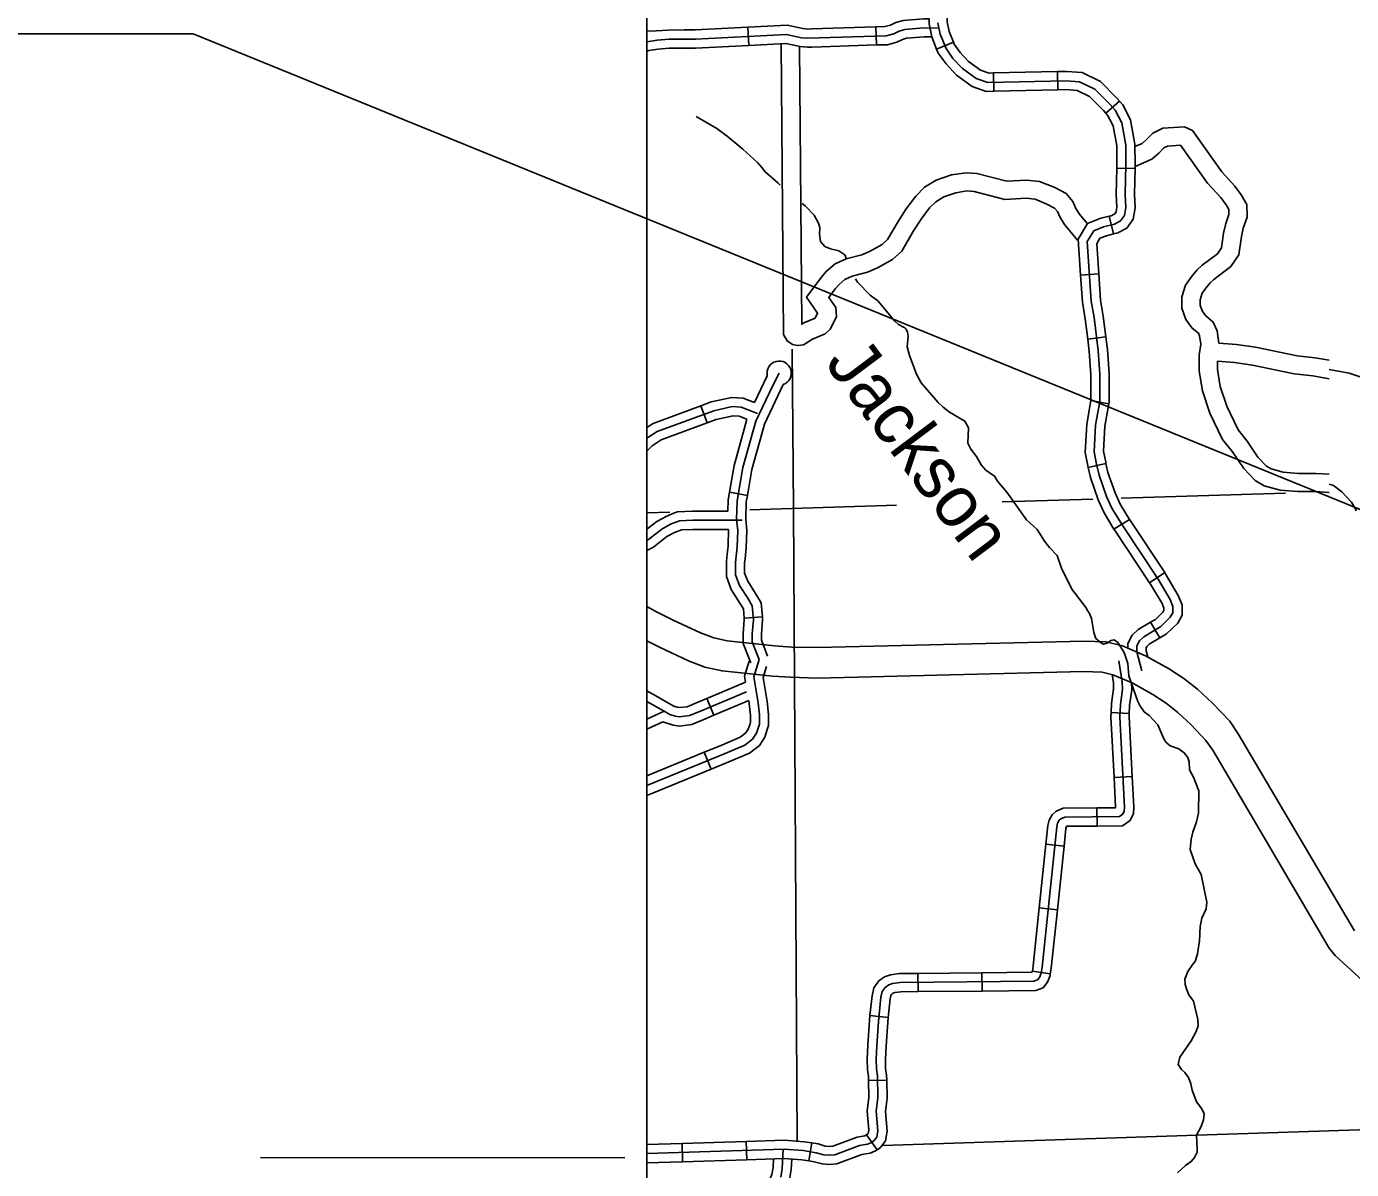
# Model space of a CAD drawing. Extents: x 1212896 to 1368412, y 378476 to 478763.
# Drawn here: x 1252291 to 1263202, y 405588 to 414998 of the extents above; entities that cross this region are included whole.
import ezdxf

# ---------------------------------------------------------------- set-up
doc = ezdxf.new("R2010")
doc.units = 0
for name, color, linetype in [('1', 7, 'Continuous'), ('Level 10', 7, 'Continuous'), ('Level 32', 7, 'Continuous'), ('Level 35', 7, 'Continuous'), ('Level 4', 7, 'Continuous'), ('Level 45', 7, 'Continuous'), ('Level 46', 7, 'Continuous'), ('Level 5', 7, 'Continuous'), ('R_Draft', 7, 'Continuous')]:
    doc.layers.add(name, color=color, linetype=linetype)

msp = doc.modelspace()

# ---------------------------------------------------------------- linework, layer by layer
at = {"layer": '1'}
msp.add_line((1254217, 405685), (1257217, 405684), dxfattribs=at)
msp.add_lwpolyline([(1257400, 437504), (1319317, 437504), (1319317, 388319), (1257400, 388319)], close=True, dxfattribs=at)
at = {"layer": 'Level 10'}
for points in [[(1258450, 409899), (1258060, 409939), (1257951, 409964), (1257842, 410006), (1257617, 410111), (1257474, 410181), (1257400, 410222)], [(1257400, 409939), (1257509, 409886), (1257743, 409776), (1257878, 409724), (1258019, 409692), (1258434, 409650)], [(1263226, 407553), (1262270, 409174), (1262199, 409278), (1262058, 409427), (1261934, 409541), (1261822, 409630), (1261694, 409713), (1261505, 409818), (1261317, 409899), (1261181, 409932), (1260997, 409938), (1258804, 409884), (1258593, 409889), (1258450, 409899)], [(1258434, 409650), (1258582, 409640), (1258804, 409634), (1260996, 409688), (1261148, 409683), (1261238, 409661), (1261395, 409594), (1261565, 409499), (1261676, 409426), (1261772, 409350), (1261882, 409249), (1262004, 409121), (1262059, 409040), (1263019, 407411), (1263068, 407350), (1265195, 405400)]]:
    msp.add_lwpolyline(points, dxfattribs=at)
at = {"layer": 'Level 32'}
for p, q in [((1259785, 414813), (1259925, 414869)), ((1260257, 414466), (1260254, 414616)), ((1260785, 414477), (1260782, 414627)), ((1261178, 414286), (1261293, 414383)), ((1261270, 413831), (1261420, 413828)), ((1261207, 413436), (1261242, 413290)), ((1260971, 412952), (1261121, 412962)), ((1261030, 412423), (1261179, 412442)), ((1261057, 411919), (1261204, 411892)), ((1261033, 411367), (1261180, 411399)), ((1261246, 410861), (1261374, 410940)), ((1261539, 410419), (1261664, 410502)), ((1261548, 410094), (1261625, 409965)), ((1261222, 409350), (1261372, 409343)), ((1261247, 408815), (1261397, 408823)), ((1261106, 408565), (1261108, 408415)), ((1260686, 408267), (1260835, 408251)), ((1260631, 407742), (1260780, 407726)), ((1260574, 407220), (1260722, 407198)), ((1259631, 407202), (1259633, 407052)), ((1260159, 407207), (1260161, 407057)), ((1259237, 406855), (1259387, 406840)), ((1259225, 406319), (1259375, 406323)), ((1257689, 405801), (1257694, 405651)), ((1258217, 405818), (1258222, 405668)), ((1258757, 405806), (1258734, 405658)), ((1259209, 405873), (1259296, 405750))]:
    msp.add_line(p, q, dxfattribs=at)
for points in [[(1259726, 415362), (1259719, 415178), (1259724, 415020), (1259745, 414914), (1259785, 414813)], [(1259876, 415356), (1259869, 415178), (1259873, 415037), (1259889, 414957), (1259925, 414869)], [(1259797, 415028), (1259816, 414935), (1259863, 414816), (1259920, 414736), (1259998, 414653), (1260112, 414571), (1260207, 414538), (1260852, 414552), (1260962, 414544), (1261089, 414483), (1261215, 414356), (1261256, 414309), (1261310, 414205), (1261343, 414022), (1261345, 413863), (1261338, 413616), (1261345, 413508), (1261333, 413442), (1261301, 413397), (1261250, 413371), (1261161, 413349), (1261079, 413316)], [(1259925, 414869), (1259931, 414852), (1259979, 414785), (1260048, 414710), (1260147, 414640), (1260219, 414615), (1260254, 414616)], [(1259785, 414813), (1259798, 414780), (1259863, 414690), (1259949, 414597), (1260078, 414505), (1260195, 414464), (1260257, 414466)], [(1260254, 414616), (1260782, 414627)], [(1260782, 414627), (1260854, 414629), (1260983, 414619), (1261134, 414546), (1261271, 414408), (1261293, 414383)], [(1260257, 414466), (1260785, 414477)], [(1260785, 414477), (1260850, 414479), (1260943, 414471), (1261046, 414422), (1261161, 414307), (1261178, 414286)], [(1261293, 414383), (1261319, 414352), (1261383, 414230), (1261419, 414029), (1261421, 413862), (1261420, 413828)], [(1261178, 414286), (1261194, 414267), (1261239, 414181), (1261269, 414015), (1261271, 413863), (1261270, 413831)], [(1261270, 413831), (1261265, 413615), (1261271, 413512), (1261263, 413471), (1261252, 413455), (1261224, 413440), (1261207, 413436)], [(1261420, 413828), (1261415, 413617), (1261422, 413504), (1261405, 413411), (1261353, 413338), (1261277, 413299), (1261242, 413290)], [(1261207, 413436), (1261138, 413419), (1261028, 413375), (1260951, 413246), (1260971, 412952)], [(1261079, 413316), (1261026, 413228), (1261059, 412737), (1261082, 412603), (1261116, 412330), (1261130, 412135), (1261130, 411912), (1261095, 411716), (1261084, 411497), (1261103, 411395), (1261123, 411304), (1261184, 411129), (1261230, 411028), (1261318, 410886), (1261609, 410447), (1261708, 410280), (1261732, 410223), (1261731, 410172), (1261710, 410134), (1261632, 410058), (1261491, 409974), (1261456, 409941), (1261434, 409899), (1261434, 409849), (1261475, 409693)], [(1261242, 413290), (1261184, 413276), (1261131, 413255), (1261104, 413209), (1261121, 412962)], [(1260971, 412952), (1260986, 412729), (1261009, 412592), (1261030, 412423)], [(1261121, 412962), (1261135, 412746), (1261157, 412614), (1261179, 412442)], [(1261030, 412423), (1261043, 412323), (1261057, 412133), (1261057, 411918)], [(1261179, 412442), (1261192, 412338), (1261207, 412138), (1261207, 411905), (1261204, 411892)], [(1261057, 411919), (1261022, 411725), (1261010, 411492), (1261030, 411381), (1261033, 411367)], [(1261204, 411892), (1261172, 411708), (1261161, 411502), (1261178, 411410), (1261180, 411399)], [(1261033, 411367), (1261052, 411284), (1261116, 411102), (1261165, 410994), (1261246, 410861)], [(1261180, 411399), (1261196, 411325), (1261255, 411158), (1261298, 411065), (1261374, 410940)], [(1261374, 410940), (1261382, 410927), (1261664, 410502)], [(1261246, 410861), (1261256, 410846), (1261539, 410419)], [(1261664, 410502), (1261674, 410487), (1261776, 410314), (1261809, 410237), (1261807, 410152), (1261771, 410087), (1261678, 409997), (1261625, 409965)], [(1261539, 410419), (1261547, 410408), (1261642, 410247), (1261658, 410208), (1261658, 410192), (1261651, 410179), (1261587, 410117), (1261548, 410094)], [(1261548, 410094), (1261446, 410033), (1261397, 409986), (1261360, 409917), (1261360, 409880)], [(1261625, 409965), (1261537, 409913), (1261518, 409894), (1261510, 409881), (1261511, 409859), (1261524, 409808)], [(1261287, 409776), (1261314, 409602), (1261317, 409541), (1261299, 409416), (1261294, 409315), (1261334, 408571), (1261331, 408539), (1261319, 408512), (1261291, 408493), (1260841, 408489), (1260809, 408476), (1260795, 408463), (1260782, 408438), (1260775, 408409), (1260654, 407254), (1260646, 407205), (1260633, 407168), (1260616, 407148), (1260587, 407137), (1259485, 407127), (1259423, 407118), (1259391, 407107), (1259362, 407087), (1259338, 407052), (1259326, 407006), (1259307, 406807), (1259293, 406607), (1259288, 406497), (1259290, 406414), (1259298, 406358), (1259302, 406178), (1259289, 406067), (1259302, 405907), (1259293, 405855), (1259271, 405826), (1259245, 405808), (1259216, 405795), (1259151, 405784), (1258948, 405708), (1258901, 405705), (1258856, 405708), (1258793, 405726), (1258686, 405743), (1258531, 405755), (1257400, 405718)], [(1261230, 409662), (1261241, 409595), (1261243, 409545), (1261226, 409423), (1261222, 409350)], [(1261391, 409596), (1261394, 409538), (1261375, 409408), (1261372, 409343)], [(1261222, 409350), (1261220, 409315), (1261247, 408815)], [(1261372, 409343), (1261371, 409315), (1261397, 408823)], [(1261247, 408815), (1261260, 408573), (1261259, 408566), (1261106, 408565)], [(1261397, 408823), (1261410, 408570), (1261406, 408519), (1261380, 408462), (1261316, 408416), (1261108, 408415)], [(1261106, 408565), (1260827, 408562), (1260769, 408539), (1260736, 408509), (1260713, 408465), (1260702, 408421), (1260686, 408267)], [(1261108, 408415), (1260856, 408413), (1260855, 408412), (1260854, 408411), (1260851, 408396), (1260835, 408251)], [(1260686, 408267), (1260631, 407742)], [(1260835, 408251), (1260780, 407726)], [(1260631, 407742), (1260581, 407264), (1260574, 407220)], [(1260780, 407726), (1260729, 407245), (1260722, 407198)], [(1260575, 407223), (1260570, 407211), (1260159, 407207)], [(1259631, 407202), (1259479, 407200), (1259406, 407190), (1259357, 407173), (1259309, 407140), (1259270, 407083), (1259254, 407018), (1259237, 406855)], [(1260159, 407207), (1259631, 407202)], [(1260722, 407198), (1260721, 407186), (1260700, 407129), (1260662, 407084), (1260602, 407061), (1260161, 407057)], [(1259633, 407052), (1259490, 407050), (1259441, 407044), (1259426, 407038), (1259417, 407032), (1259409, 407021), (1259402, 406993), (1259387, 406840)], [(1260161, 407057), (1259633, 407052)], [(1259237, 406855), (1259233, 406813), (1259220, 406611), (1259214, 406497), (1259217, 406407), (1259224, 406352), (1259225, 406319)], [(1259387, 406840), (1259383, 406801), (1259369, 406603), (1259364, 406496), (1259366, 406420), (1259374, 406364), (1259375, 406323)], [(1259225, 406319), (1259228, 406181), (1259215, 406068), (1259228, 405911), (1259223, 405885), (1259219, 405880), (1259209, 405873)], [(1259375, 406323), (1259378, 406174), (1259366, 406066), (1259379, 405903), (1259365, 405823), (1259324, 405770), (1259296, 405750)], [(1257689, 405801), (1257400, 405792)], [(1258217, 405818), (1257689, 405801)], [(1258757, 405806), (1258695, 405816), (1258533, 405828), (1258217, 405818)], [(1259209, 405873), (1259209, 405872), (1259194, 405866), (1259132, 405855), (1258932, 405781), (1258901, 405778), (1258869, 405781), (1258809, 405798), (1258757, 405806)], [(1259296, 405750), (1259283, 405741), (1259238, 405721), (1259171, 405710), (1258964, 405633), (1258901, 405628), (1258842, 405633), (1258777, 405651), (1258734, 405658)], [(1257694, 405651), (1257400, 405642)], [(1258222, 405668), (1257694, 405651)], [(1258734, 405658), (1258677, 405667), (1258529, 405678), (1258222, 405668)]]:
    msp.add_lwpolyline(points, dxfattribs=at)
at = {"layer": 'Level 35'}
for points in [[(1257806, 414257), (1257977, 414158), (1258062, 414095), (1258190, 413989), (1258311, 413879), (1258350, 413836), (1258371, 413804), (1258477, 413712), (1258498, 413692)], [(1258679, 413542), (1258704, 413522), (1258778, 413444), (1258814, 413378), (1258825, 413344), (1258820, 413289), (1258830, 413229), (1258866, 413188), (1258911, 413167), (1258980, 413151), (1259030, 413118), (1259043, 413086)], [(1259117, 412922), (1259135, 412892), (1259238, 412785), (1259302, 412739), (1259442, 412572), (1259473, 412545), (1259523, 412517), (1259536, 412505), (1259546, 412482), (1259550, 412448), (1259544, 412361), (1259562, 412289), (1259621, 412135), (1259658, 412065), (1259799, 411902), (1259840, 411863), (1259891, 411823), (1260017, 411748), (1260049, 411693), (1260043, 411568), (1260068, 411519), (1260113, 411457), (1260153, 411389), (1260191, 411346), (1260261, 411296), (1260286, 411255), (1260364, 411164), (1260527, 410937), (1260615, 410857), (1260674, 410760), (1260715, 410708), (1260779, 410642), (1260815, 410538), (1260898, 410367), (1260989, 410248)], [(1260989, 410248), (1261018, 410213), (1261025, 410193), (1261041, 410172), (1261060, 410125), (1261080, 410008), (1261098, 409960), (1261143, 409921), (1261160, 409914), (1261190, 409922), (1261219, 409942), (1261248, 409948), (1261278, 409926), (1261331, 409843), (1261360, 409754), (1261369, 409653), (1261443, 409441), (1261458, 409409), (1261495, 409356), (1261537, 409326), (1261607, 409248), (1261656, 409132), (1261673, 409107), (1261710, 409077), (1261780, 409051), (1261825, 409019), (1261855, 408979), (1261865, 408943), (1261868, 408878), (1261900, 408819), (1261946, 408706), (1261941, 408520), (1261925, 408449), (1261895, 408365), (1261883, 408306), (1261875, 408223), (1261914, 408104), (1261963, 408017), (1262011, 407789), (1262005, 407735), (1261969, 407656), (1261955, 407588), (1261951, 407471), (1261934, 407363), (1261915, 407299), (1261895, 407278), (1261855, 407219), (1261831, 407154), (1261832, 407112), (1261844, 407075), (1261864, 407026), (1261901, 406974), (1261936, 406823), (1261939, 406771), (1261924, 406723), (1261882, 406646), (1261789, 406513), (1261776, 406451), (1261803, 406412), (1261830, 406386), (1261861, 406345), (1261880, 406293), (1261891, 406240), (1261926, 406146), (1261969, 406087), (1261989, 406046), (1261984, 405996), (1261965, 405942), (1261927, 405870), (1261931, 405756)], [(1261931, 405756), (1261931, 405731), (1261910, 405686), (1261885, 405655), (1261835, 405620), (1261768, 405561)]]:
    msp.add_lwpolyline(points, dxfattribs=at)
at = {"layer": 'Level 4'}
msp.add_lwpolyline([(1263432, 405920), (1259342, 405784)], dxfattribs=at)
at = {"layer": 'Level 45'}
for p, q in [((1258239, 414843), (1258232, 414993)), ((1259290, 414846), (1259285, 414995)), ((1257896, 411735), (1257844, 411876)), ((1258079, 411163), (1258227, 411137)), ((1258201, 410127), (1258351, 410139)), ((1257952, 409328), (1257894, 409466)), ((1257929, 408884), (1257872, 409023))]:
    msp.add_line(p, q, dxfattribs=at)
for points in [[(1259806, 414985), (1259679, 414986), (1259525, 414974), (1259477, 414960), (1259433, 414938), (1259370, 414922), (1258724, 414901), (1258673, 414905), (1258550, 414933), (1257799, 414894), (1257582, 414893), (1257484, 414887), (1257400, 414873)], [(1257708, 414970), (1257579, 414969), (1257476, 414963), (1257400, 414959)], [(1258232, 414993), (1257797, 414970), (1257708, 414970)], [(1258757, 414978), (1258726, 414977), (1258685, 414981), (1258556, 415010), (1258232, 414993)], [(1259285, 414995), (1258757, 414978)], [(1259722, 415062), (1259677, 415062), (1259511, 415049), (1259449, 415032), (1259406, 415010), (1259360, 414998), (1259285, 414995)], [(1258762, 414828), (1258721, 414827), (1258661, 414833), (1258544, 414859), (1258239, 414843)], [(1259745, 414912), (1259682, 414912), (1259538, 414901), (1259504, 414891), (1259459, 414869), (1259381, 414848), (1259290, 414846)], [(1257708, 414820), (1257584, 414819), (1257493, 414813), (1257417, 414801), (1257400, 414793)], [(1258239, 414843), (1257801, 414820), (1257708, 414820)], [(1259290, 414846), (1258762, 414828)], [(1258489, 412144), (1258436, 412043), (1258297, 411750), (1258191, 411366), (1258143, 411093), (1258138, 410939), (1258148, 410848), (1258143, 410713), (1258129, 410584), (1258129, 410483), (1258162, 410397), (1258230, 410291), (1258268, 410229), (1258278, 410114), (1258268, 409998), (1258268, 409931), (1258292, 409869), (1258324, 409786)], [(1258391, 412123), (1258286, 411902)], [(1258522, 412050), (1258367, 411724), (1258345, 411644)], [(1257844, 411876), (1257929, 411908), (1258098, 411945), (1258192, 411938), (1258286, 411902)], [(1257400, 411698), (1257451, 411730), (1257844, 411876)], [(1257400, 411609), (1257485, 411663), (1257950, 411835), (1258103, 411869), (1258175, 411864), (1258310, 411813)], [(1257442, 411547), (1257518, 411595), (1257896, 411735)], [(1257896, 411735), (1257971, 411763), (1258109, 411794), (1258159, 411790), (1258223, 411766)], [(1258223, 411766), (1258201, 411683)], [(1258201, 411683), (1258118, 411383), (1258079, 411163)], [(1258345, 411644), (1258264, 411350), (1258227, 411137)], [(1257400, 411502), (1257442, 411547)], [(1258079, 411163), (1258068, 411100), (1258066, 411008)], [(1258227, 411137), (1258218, 411085), (1258214, 410942), (1258223, 410850), (1258218, 410708), (1258208, 410616)], [(1257628, 410993), (1257563, 410968), (1257482, 410924), (1257400, 410860)], [(1258183, 410934), (1257777, 410933), (1257667, 410928), (1257595, 410900), (1257523, 410861), (1257413, 410775), (1257400, 410769)], [(1258066, 411008), (1257775, 411008), (1257651, 411003), (1257628, 410993)], [(1257684, 410854), (1257627, 410831), (1257564, 410798), (1257453, 410711), (1257400, 410685)], [(1258073, 410858), (1257779, 410858), (1257683, 410854), (1257684, 410854)], [(1258073, 410858), (1258068, 410719), (1258059, 410632)], [(1258059, 410632), (1258054, 410588), (1258054, 410469), (1258095, 410363), (1258166, 410251), (1258195, 410205), (1258201, 410127)], [(1258208, 410616), (1258204, 410580), (1258204, 410497), (1258230, 410431), (1258293, 410331), (1258341, 410253), (1258351, 410139)], [(1258201, 410127), (1258202, 410114), (1258193, 410001), (1258193, 409917), (1258222, 409841), (1258255, 409759)], [(1258351, 410139), (1258353, 410114), (1258343, 409995), (1258343, 409945), (1258362, 409896), (1258394, 409814)], [(1257400, 408749), (1258045, 409013), (1258206, 409081), (1258270, 409131), (1258302, 409180), (1258327, 409255), (1258327, 409330), (1258316, 409430), (1258281, 409644), (1258324, 409786)], [(1258212, 409599), (1258204, 409649), (1258242, 409774)], [(1258391, 409210), (1258402, 409243), (1258402, 409334), (1258391, 409440), (1258357, 409639), (1258386, 409730)], [(1257400, 409528), (1257473, 409487)], [(1257400, 409442), (1257541, 409362), (1257589, 409334), (1257632, 409319), (1257669, 409315), (1257750, 409325), (1257841, 409362), (1258219, 409521)], [(1257894, 409466), (1258212, 409599)], [(1257473, 409487), (1257579, 409427), (1257621, 409403), (1257649, 409393), (1257669, 409391), (1257731, 409398), (1257813, 409432), (1257894, 409466)], [(1257952, 409328), (1258239, 409448)], [(1258249, 409258), (1258252, 409268), (1258252, 409326), (1258239, 409448)], [(1257400, 409295), (1257541, 409362)], [(1257532, 409274), (1257615, 409246), (1257669, 409239), (1257769, 409252), (1257870, 409293), (1257952, 409328)], [(1257400, 409212), (1257532, 409274)], [(1257872, 409023), (1258017, 409082), (1258167, 409146), (1258214, 409182), (1258234, 409213), (1258249, 409258)], [(1257929, 408884), (1258074, 408944), (1258244, 409015), (1258326, 409079), (1258370, 409148), (1258391, 409210)], [(1257400, 408830), (1257872, 409023)], [(1257440, 408684), (1257929, 408884)], [(1257400, 408668), (1257440, 408684)], [(1258521, 405754), (1258515, 405596), (1258504, 405525)], [(1258442, 405675), (1258439, 405604), (1258430, 405546), (1258399, 405469), (1258388, 405411), (1258393, 405341), (1258421, 405273), (1258450, 405228), (1258452, 405222)], [(1258592, 405674), (1258589, 405588), (1258575, 405505), (1258543, 405426), (1258539, 405403), (1258541, 405376), (1258554, 405343), (1258585, 405296), (1258593, 405274)]]:
    msp.add_lwpolyline(points, dxfattribs=at)
msp.add_arc((1258489, 412144), 100, 289.4935, 192.0216, dxfattribs=at)
at = {"layer": 'Level 46'}
for points in [[(1258506, 414857), (1258526, 412463), (1258554, 412409), (1258599, 412381), (1258642, 412371), (1258689, 412377), (1258763, 412425), (1258868, 412467), (1258909, 412507), (1258960, 412609), (1258957, 412684), (1258898, 412767), (1258951, 412838), (1258983, 412874), (1259031, 412916), (1259090, 412943), (1259217, 412975), (1259299, 413011), (1259423, 413080), (1259500, 413148), (1259596, 413316), (1259659, 413411), (1259728, 413504), (1259779, 413556), (1259845, 413596), (1259944, 413630), (1260034, 413644), (1260094, 413639), (1260348, 413574), (1260522, 413584), (1260598, 413576), (1260694, 413536), (1260757, 413503), (1260780, 413476), (1260800, 413431), (1260838, 413367), (1260946, 413238)], [(1258656, 414833), (1258675, 412547), (1258693, 412559), (1258785, 412596), (1258786, 412597), (1258806, 412637), (1258714, 412770), (1258834, 412933), (1258877, 412981), (1258949, 413043), (1259040, 413085), (1259169, 413118), (1259233, 413145), (1259336, 413203), (1259382, 413244), (1259468, 413394), (1259536, 413497), (1259614, 413602), (1259686, 413675), (1259781, 413732), (1259908, 413777), (1260028, 413794), (1260118, 413788), (1260363, 413725), (1260525, 413734), (1260634, 413723), (1260758, 413672), (1260852, 413622), (1260908, 413557), (1260933, 413500), (1260961, 413454), (1261028, 413374)], [(1261419, 414009), (1261479, 414036), (1261512, 414064), (1261566, 414121), (1261649, 414161), (1261827, 414173), (1261893, 414141)], [(1261893, 414141), (1262134, 413803), (1262241, 413685), (1262295, 413613), (1262339, 413533), (1262342, 413428), (1262311, 413337), (1262297, 413270), (1262275, 413119), (1262208, 413021), (1262068, 412916), (1262037, 412889), (1262002, 412845), (1261973, 412803), (1261956, 412749), (1261956, 412705), (1261973, 412656), (1262001, 412618), (1262064, 412564), (1262096, 412493), (1262111, 412391)], [(1261421, 413846), (1261559, 413907), (1261615, 413955), (1261656, 413998), (1261687, 414013), (1261795, 414020)], [(1261795, 414020), (1262017, 413709), (1262125, 413590), (1262169, 413531), (1262191, 413492), (1262192, 413451), (1262166, 413377), (1262149, 413296), (1262132, 413175), (1262098, 413126), (1261972, 413032), (1261928, 412992), (1261882, 412935), (1261836, 412869), (1261806, 412773), (1261806, 412680), (1261839, 412585), (1261891, 412515), (1261941, 412473), (1261950, 412451), (1261961, 412382), (1261947, 412295), (1261949, 412161), (1261976, 411998), (1262036, 411814), (1262141, 411598), (1262221, 411495), (1262315, 411358), (1262408, 411261), (1262482, 411217), (1262614, 411182), (1262759, 411169), (1262906, 411169), (1263017, 411161)], [(1263017, 412250), (1262904, 412270), (1262755, 412287), (1262413, 412357), (1262255, 412380), (1262111, 412391)], [(1263017, 412098), (1262883, 412121), (1262731, 412139), (1262387, 412209), (1262238, 412231), (1262098, 412242)], [(1262098, 412242), (1262099, 412174), (1262122, 412034), (1262176, 411871), (1262269, 411678), (1262342, 411584), (1262432, 411453), (1262502, 411379), (1262540, 411356), (1262640, 411330), (1262766, 411319), (1262911, 411319), (1263017, 411312)], [(1263582, 412013), (1263183, 412145), (1263017, 412174)], [(1263017, 411231), (1263055, 411220), (1263124, 411168), (1263201, 411081), (1263244, 411011)]]:
    msp.add_lwpolyline(points, dxfattribs=at)
at = {"layer": 'Level 5'}
for points in [[(1258637, 405822), (1258606, 411031), (1258596, 412342)], [(1262659, 411156), (1261305, 411115)], [(1259454, 411058), (1258247, 411020)], [(1261072, 411107), (1260326, 411084)], [(1257588, 411000), (1257400, 410994)]]:
    msp.add_lwpolyline(points, dxfattribs=at)
at = {"layer": 'R_Draft'}
for q in [(1233980, 414939), (1283026, 402970)]:
    msp.add_line((1253662, 414939), q, dxfattribs=at)

# ---------------------------------------------------------------- texts
at = {"layer": 'Level 35'}
msp.add_text('Jackson', height=422.4, rotation=306.8596, dxfattribs=at).set_placement((1258857, 412226))

doc.saveas('drawing.dxf')
